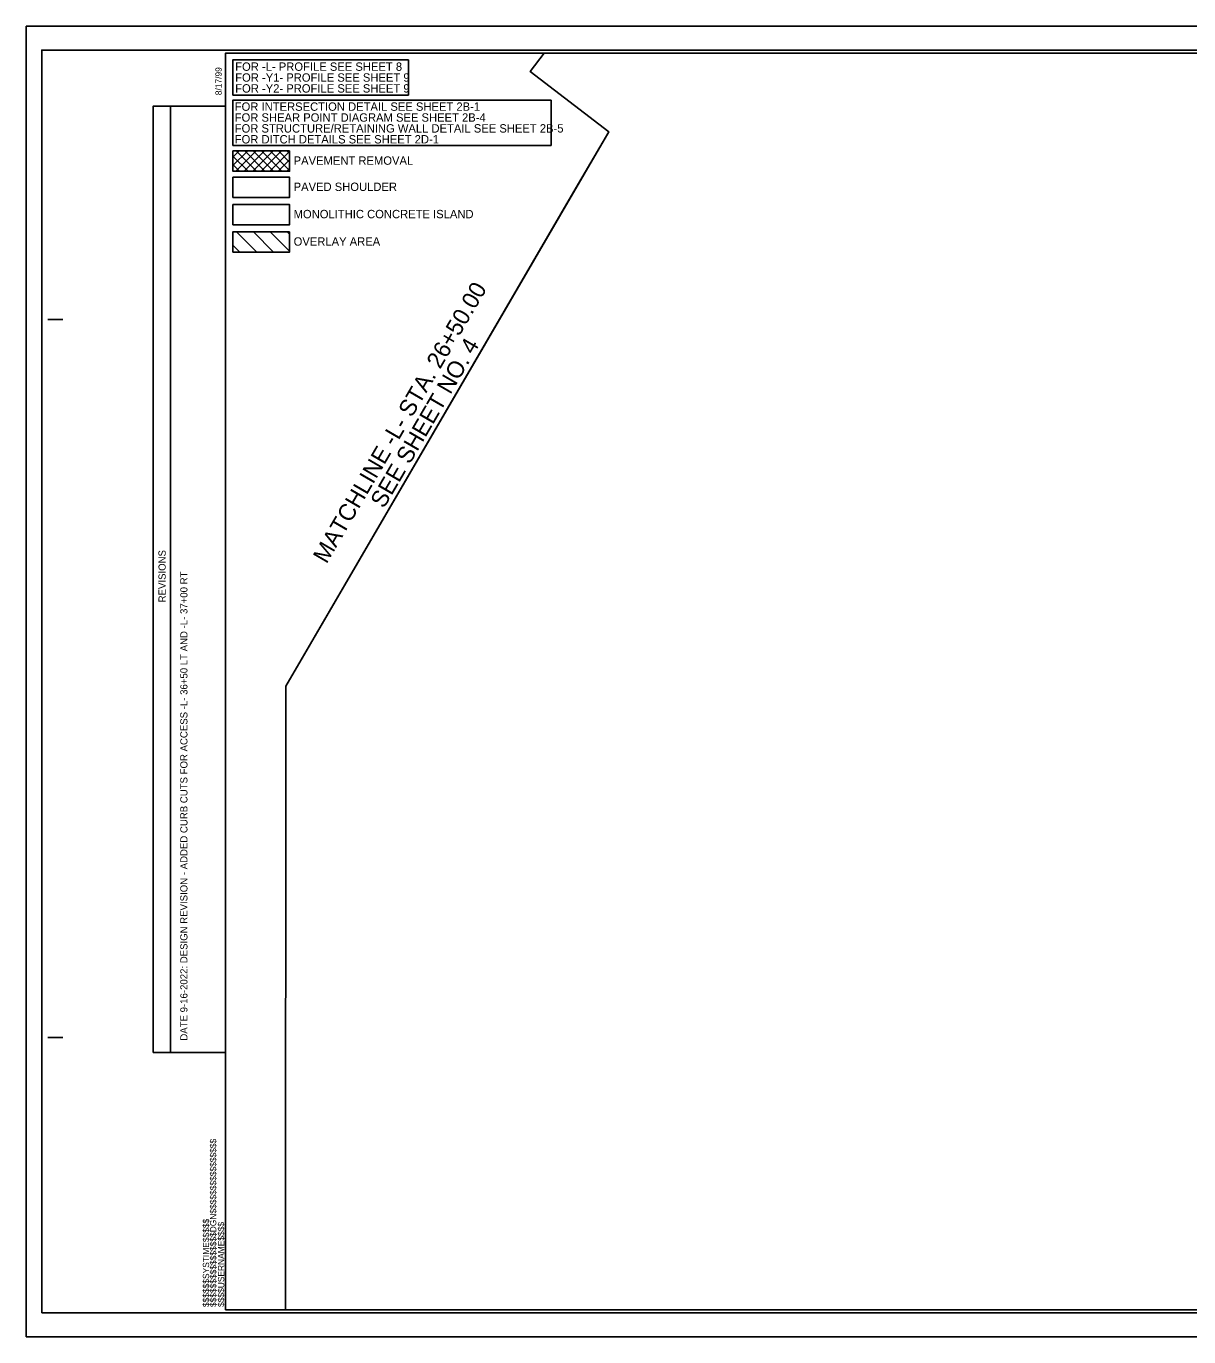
# Model space of a CAD drawing. Extents: x 1619045 to 1620988, y 897376 to 898471.
# Drawn here: x 1619045 to 1620016, y 897376 to 898471 of the extents above; entities that cross this region are included whole.
import ezdxf

# ---------------------------------------------------------------- set-up
doc = ezdxf.new("R2010")
doc.units = 0
for name, color, linetype in [('Matchline', 7, 'Continuous'), ('Matchline Text', 7, 'Continuous'), ('Old_Level_10', 7, 'Continuous'), ('Old_Level_40', 7, 'Continuous'), ('Prop DSN Text', 7, 'Continuous'), ('Prop Rem of Exist Asph Pvmt', 7, 'Continuous'), ('Prop Shade Medium', 7, 'Continuous'), ('Sheet Block Revision CELL', 7, 'Continuous'), ('Sheet Cutting Line CELL', 7, 'Continuous'), ('Sheet Layout Plan Border', 7, 'Continuous'), ('Sheet Plan CELL', 7, 'Continuous'), ('Sheet Plan Layout CELL', 7, 'Continuous'), ('Sheet Plot Border Inside CELL', 7, 'Continuous'), ('Sheet Plot Border Outside CELL', 7, 'Continuous')]:
    doc.layers.add(name, color=color, linetype=linetype)

msp = doc.modelspace()

# ---------------------------------------------------------------- linework, layer by layer
at = {"layer": 'Matchline'}
msp.add_line((1619262.1, 897919.5), (1619531.9, 898382.6), dxfattribs=at)
at = {"layer": 'Old_Level_10'}
for p, q in [((1619220.9, 898299), (1619237.9, 898282.1)), ((1619235.1, 898299), (1619252, 898282.1)), ((1619249.2, 898299), (1619265.3, 898282.9)), ((1619263.4, 898299), (1619265.3, 898297)), ((1619218, 898287.8), (1619223.7, 898282.1))]:
    msp.add_line(p, q, dxfattribs=at)
at = {"layer": 'Old_Level_40'}
for points in [[(1619364.6, 898442.8), (1619218, 898442.8), (1619218, 898413.2), (1619364.6, 898413.2)], [(1619483.7, 898409), (1619218, 898409), (1619218, 898371.1), (1619483.7, 898371.1)], [(1619265.3, 898366.6), (1619218, 898366.6), (1619218, 898349.6), (1619265.3, 898349.6)], [(1619265.3, 898344.6), (1619218, 898344.6), (1619218, 898327.7), (1619265.3, 898327.7)], [(1619265.3, 898321.8), (1619218, 898321.8), (1619218, 898304.9), (1619265.3, 898304.9)], [(1619265.3, 898299), (1619218, 898299), (1619218, 898282.1), (1619265.3, 898282.1)]]:
    msp.add_lwpolyline(points, close=True, dxfattribs=at)
at = {"layer": 'Prop Rem of Exist Asph Pvmt'}
for p, q in [((1619218, 898354.3), (1619230.3, 898366.6)), ((1619218, 898361.3), (1619223.2, 898366.6)), ((1619218, 898362.2), (1619230.6, 898349.6)), ((1619220.4, 898349.6), (1619237.4, 898366.6)), ((1619220.7, 898366.6), (1619237.7, 898349.6)), ((1619227.5, 898349.6), (1619244.4, 898366.6)), ((1619227.8, 898366.6), (1619244.7, 898349.6)), ((1619234.6, 898349.6), (1619251.5, 898366.6)), ((1619234.9, 898366.6), (1619251.8, 898349.6)), ((1619241.6, 898349.6), (1619258.6, 898366.6)), ((1619241.9, 898366.6), (1619258.9, 898349.6)), ((1619248.7, 898349.6), (1619265.3, 898366.2)), ((1619249, 898366.6), (1619265.3, 898350.3)), ((1619256.1, 898366.6), (1619265.3, 898357.3)), ((1619263.1, 898366.6), (1619265.3, 898364.4)), ((1619218, 898355.1), (1619223.5, 898349.6)), ((1619255.8, 898349.6), (1619265.3, 898359.2)), ((1619262.9, 898349.6), (1619265.3, 898352.1))]:
    msp.add_line(p, q, dxfattribs=at)
at = {"layer": 'Prop Shade Medium'}
for points in [[(1619218, 898344.6), (1619265.3, 898344.6), (1619265.3, 898327.7), (1619218, 898327.7)], [(1619218, 898321.8), (1619265.3, 898321.8), (1619265.3, 898304.9), (1619218, 898304.9)]]:
    msp.add_lwpolyline(points, close=True, dxfattribs=at)
at = {"layer": 'Sheet Block Revision CELL'}
msp.add_line((1619165.8, 897613.3), (1619165.8, 898403.9), dxfattribs=at)
msp.add_lwpolyline([(1619151.3, 897613.3), (1619151.3, 898403.9), (1619211.8, 898403.9), (1619211.8, 897613.3)], close=True, dxfattribs=at)
at = {"layer": 'Sheet Cutting Line CELL'}
for p, q in [((1620728.8, 898470.8), (1619045.3, 898470.8)), ((1619045.3, 898470.8), (1619045.3, 897375.8)), ((1619045.3, 897375.8), (1620728.8, 897375.8))]:
    msp.add_line(p, q, dxfattribs=at)
at = {"layer": 'Sheet Layout Plan Border'}
msp.add_lwpolyline([(1619504.8, 898336.1), (1619262.1, 897919.5), (1619261.8, 897398.3), (1620711.8, 897398.3), (1620711.8, 897792), (1620549.3, 897792), (1620534.5, 897965.9), (1620511.8, 898225.2), (1620511.7, 898448.3), (1620082.8, 898448.3), (1619478.1, 898448.3), (1619466.3, 898432.9), (1619531.9, 898382.6)], close=True, dxfattribs=at)
at = {"layer": 'Sheet Plan CELL'}
for p, q in [((1619211.8, 898448.3), (1619211.8, 898448.3)), ((1619063.3, 898225.8), (1619075.8, 898225.8)), ((1619063.3, 897625.8), (1619075.8, 897625.8)), ((1619211.8, 897398.3), (1619211.8, 897398.3))]:
    msp.add_line(p, q, dxfattribs=at)
for points in [[(1620711.8, 898448.3), (1619211.8, 898448.3), (1619211.8, 897398.3), (1620711.8, 897398.3)], [(1619211.8, 897398.3), (1619211.8, 898448.3), (1620511.7, 898448.3), (1620511.8, 898298.2), (1620711.8, 898298.2), (1620711.8, 897398.3)]]:
    msp.add_lwpolyline(points, close=True, dxfattribs=at)
at = {"layer": 'Sheet Plan Layout CELL'}
msp.add_lwpolyline([(1619211.8, 898448.3), (1619211.8, 897398.3), (1620711.8, 897398.3), (1620711.8, 898236.8), (1620511.7, 898236.8), (1620511.7, 898448.3)], close=True, dxfattribs=at)
at = {"layer": 'Sheet Plot Border Inside CELL'}
msp.add_lwpolyline([(1619058.3, 897395.8), (1620724.3, 897395.8), (1620724.3, 898450.8), (1619058.3, 898450.8)], close=True, dxfattribs=at)
at = {"layer": 'Sheet Plot Border Outside CELL'}
msp.add_lwpolyline([(1619045.3, 897375.8), (1620728.8, 897375.8), (1620728.8, 898470.8), (1619045.3, 898470.8)], close=True, dxfattribs=at)

# ---------------------------------------------------------------- texts
at = {"layer": 'Matchline Text'}
for s, p in [('MATCHLINE -L- STA. 26+50.00', (1619296.2, 898021)), ('SEE SHEET NO. 4', (1619344.1, 898067.2))]:
    msp.add_text(s, height=14, rotation=59.769, dxfattribs=at).set_placement(p)
at = {"layer": 'Prop DSN Text'}
for s, p in [('FOR -L- PROFILE SEE SHEET 8', (1619219.9, 898433.5)), ('FOR -Y1- PROFILE SEE SHEET 9', (1619219.9, 898424.4)), ('FOR -Y2- PROFILE SEE SHEET 9', (1619219.9, 898415.3)), ('FOR INTERSECTION DETAIL SEE SHEET 2B-1', (1619219.5, 898400.1)), ('FOR SHEAR POINT DIAGRAM SEE SHEET 2B-4', (1619219.5, 898391)), ('FOR STRUCTURE/RETAINING WALL DETAIL SEE SHEET 2B-5', (1619219.5, 898381.9)), ('FOR DITCH DETAILS SEE SHEET 2D-1', (1619219.5, 898372.8)), ('PAVEMENT REMOVAL', (1619268.7, 898355)), ('PAVED SHOULDER', (1619268.7, 898333.1)), ('MONOLITHIC CONCRETE ISLAND', (1619268.7, 898310.3)), ('OVERLAY AREA', (1619268.7, 898287.4))]:
    msp.add_text(s, height=7, dxfattribs=at).set_placement(p)
at = {"layer": 'Sheet Block Revision CELL'}
for s, p in [('REVISIONS', (1619161.8, 897989.4)), ('DATE 9-16-2022: DESIGN REVISION - ADDED CURB CUTS FOR ACCESS -L- 36+50 LT AND -L- 37+00 RT', (1619180, 897623.2))]:
    msp.add_text(s, height=6, rotation=90, dxfattribs=at).set_placement(p)
at = {"layer": 'Sheet Plan CELL'}
for s, p in [('8/17/99', (1619208.6, 898413.1)), ('$$$$$$$$$$$$$$$$DGN$$$$$$$$$$$$$$$$', (1619204.1, 897400.6)), ('$$$$$$SYSTIME$$$$$', (1619198.1, 897400.6)), ('$$$$USERNAME$$$$', (1619210.7, 897400.7))]:
    msp.add_text(s, height=5.25, rotation=90, dxfattribs=at).set_placement(p)

doc.saveas('drawing.dxf')
